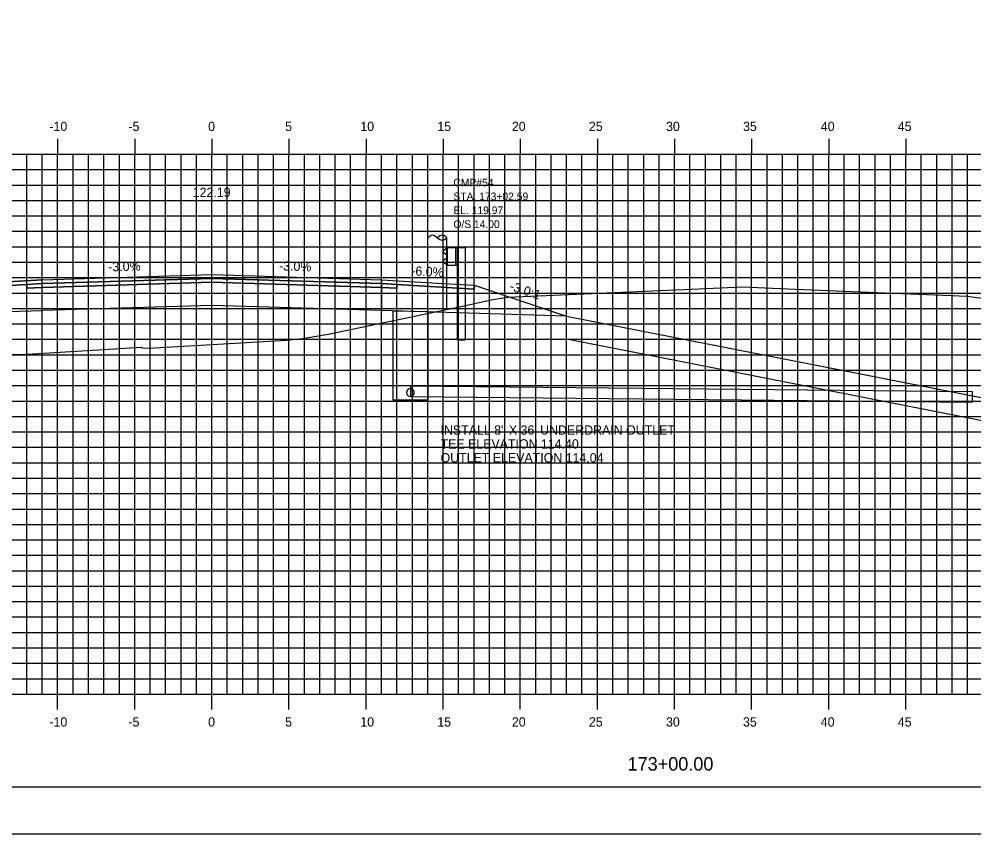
# Model space of a CAD drawing. Extents: x 850598 to 870284, y 366541 to 366651.
# Drawn here: x 856847.6 to 856909.5, y 366541.2 to 366594 of the extents above; entities that cross this region are included whole.
import ezdxf

# ---------------------------------------------------------------- set-up
doc = ezdxf.new("R2010")
doc.units = 0
for name, color, linetype in [('ANNOTATION', 7, 'Continuous'), ('BORDER', 7, 'Continuous'), ('D_Drainage_Culvert', 7, 'Continuous'), ('D_Drainage_RipRap', 7, 'Continuous'), ('D_Drainage_Underdrain', 7, 'Continuous'), ('D_Drainage_Underdrain_06in', 7, 'Continuous'), ('D_Guardrail_Beam_Rt', 7, 'Continuous'), ('D_Roadway_Centerline', 7, 'Continuous'), ('D_Roadway_Centerline_Text', 7, 'Continuous'), ('D_Roadway_Edge_Shoulder', 7, 'Continuous'), ('D_Roadway_Edge_TW', 7, 'Continuous'), ('D_Roadway_Pavement', 7, 'Continuous'), ('D_Roadway_SlopeLines', 7, 'Continuous'), ('D_Roadway_SubGrade', 7, 'Continuous'), ('D_Text_Monospaced', 7, 'Continuous'), ('H_V ANNOTATION', 7, 'Continuous'), ('MAJOR', 7, 'Continuous'), ('MINOR', 7, 'Continuous'), ('PLOT BOUNDARY', 7, 'Continuous'), ('S_Roadway_Centerline', 7, 'Continuous'), ('S_Utilities_Pole_Joint', 7, 'Continuous')]:
    doc.layers.add(name, color=color, linetype=linetype)

msp = doc.modelspace()

# ---------------------------------------------------------------- linework, layer by layer
at = {"layer": 'BORDER'}
msp.add_line((856815.08, 366544.225), (856975.08, 366544.225), dxfattribs=at)
at = {"layer": 'D_Drainage_Culvert'}
msp.add_lwpolyline([(856872.955, 366569.522), (856909.401, 366569.158), (856909.408, 366569.825), (856872.962, 366570.189)], close=True, dxfattribs=at)
at = {"layer": 'D_Drainage_RipRap'}
msp.add_lwpolyline([(856960.08, 366559.621), (856960.08, 366556.34), (856942.572, 366559.775), (856941.71, 366561.725), (856883.08, 366573.229), (856883.08, 366574.729), (856941.71, 366563.225)], close=True, dxfattribs=at)
at = {"layer": 'D_Drainage_Underdrain'}
msp.add_lwpolyline([(856874.08, 366575.022), (856874.08, 366569.272), (856871.83, 366569.272), (856871.83, 366575.067)], close=True, dxfattribs=at)
at = {"layer": 'D_Drainage_Underdrain_06in'}
msp.add_lwpolyline([(856872.955, 366570.022), (856872.878, 366570.01), (856872.808, 366569.975), (856872.753, 366569.919), (856872.717, 366569.85), (856872.705, 366569.772), (856872.717, 366569.695), (856872.753, 366569.625), (856872.808, 366569.57), (856872.878, 366569.535), (856872.955, 366569.522), (856873.032, 366569.535), (856873.102, 366569.57), (856873.157, 366569.625), (856873.193, 366569.695), (856873.205, 366569.772), (856873.193, 366569.85), (856873.157, 366569.919), (856873.102, 366569.975), (856873.032, 366570.01)], close=True, dxfattribs=at)
at = {"layer": 'D_Guardrail_Beam_Rt'}
for p, q in [((856875.261, 366579.088), (856875.118, 366578.988)), ((856875.118, 366578.845), (856875.313, 366578.709)), ((856875.351, 366579.108), (856875.278, 366579.095)), ((856875.347, 366578.645), (856875.347, 366578.553)), ((856875.351, 366579.182), (856876.039, 366579.182)), ((856875.351, 366578.016), (856875.351, 366579.182)), ((856875.872, 366579.182), (856875.872, 366578.016)), ((856875.976, 366579.182), (856875.976, 366578.016)), ((856876.039, 366579.182), (856876.509, 366579.182)), ((856876.039, 366579.182), (856876.039, 366578.016)), ((856876.509, 366579.182), (856876.509, 366573.182)), ((856875.313, 366578.489), (856875.118, 366578.353)), ((856875.118, 366578.21), (856875.261, 366578.11)), ((856875.278, 366578.103), (856875.351, 366578.09)), ((856876.039, 366578.016), (856875.351, 366578.016)), ((856876.018, 366573.182), (856876.018, 366578.016)), ((856876.018, 366573.182), (856876.509, 366573.182))]:
    msp.add_line(p, q, dxfattribs=at)
for centre, major_axis, start_param, end_param in [((856875.168, 366578.917), (-0.0877, 0), 5.323254, 7.243116), ((856875.285, 366579.054), (-0.0417, 0), 4.886922, 5.323254), ((856875.268, 366578.645), (0.0789, 0), 0, 0.959931), ((856875.168, 366578.281), (-0.0877, 0), 5.323254, 7.243116), ((856875.285, 366578.144), (-0.0417, 0), 0.959931, 1.396263), ((856875.268, 366578.553), (0.0789, 0), 5.323254, 6.283185)]:
    msp.add_ellipse(centre, major_axis=major_axis, ratio=0.995501, start_param=start_param, end_param=end_param, dxfattribs=at)
at = {"layer": 'D_Roadway_Centerline'}
msp.add_lwpolyline([(856829.42, 366572.013), (856829.835, 366571.992), (856830.25, 366571.917), (856830.665, 366571.79), (856831.08, 366571.609), (856837.336, 366574.737), (856841.08, 366576.609), (856843.08, 366576.729), (856849.08, 366577.089), (856860.08, 366577.419), (856871.08, 366577.089), (856875.08, 366576.849), (856877.08, 366576.729), (856883.08, 366574.729), (856941.71, 366563.225), (856960.08, 366559.621)], dxfattribs=at)
at = {"layer": 'D_Roadway_Edge_Shoulder'}
for points in [[(856849.08, 366577.089), (856843.08, 366576.729), (856843.08, 366576.729), (856841.08, 366576.609), (856841.08, 366576.359), (856848.08, 366576.779), (856849.08, 366576.839)], [(856871.08, 366577.089), (856875.08, 366576.849), (856875.08, 366576.849), (856877.08, 366576.729), (856877.08, 366576.479), (856872.08, 366576.779), (856871.08, 366576.839)]]:
    msp.add_lwpolyline(points, close=True, dxfattribs=at)
at = {"layer": 'D_Roadway_Edge_TW'}
msp.add_lwpolyline([(856849.08, 366576.839), (856849.08, 366577.089), (856860.08, 366577.419), (856871.08, 366577.089), (856871.08, 366576.839), (856860.08, 366577.169)], close=True, dxfattribs=at)
at = {"layer": 'D_Roadway_Pavement'}
for points in [[(856849.08, 366576.839), (856848.08, 366576.779), (856848.08, 366576.529), (856849.08, 366576.589)], [(856849.08, 366576.589), (856849.08, 366576.839), (856860.08, 366577.169), (856871.08, 366576.839), (856871.08, 366576.589), (856860.08, 366576.919)], [(856871.08, 366576.839), (856872.08, 366576.779), (856872.08, 366576.529), (856871.08, 366576.589)]]:
    msp.add_lwpolyline(points, close=True, dxfattribs=at)
at = {"layer": 'D_Roadway_SlopeLines'}
msp.add_lwpolyline([(856883.08, 366574.729), (856960.08, 366559.621)], dxfattribs=at)
at = {"layer": 'D_Roadway_SubGrade'}
for points in [[(856849.08, 366575.089), (856849.08, 366576.589), (856860.08, 366576.919), (856871.08, 366576.589), (856871.08, 366575.089), (856860.08, 366575.419)], [(856849.08, 366576.589), (856848.08, 366576.529), (856848.08, 366576.779), (856841.08, 366576.359), (856841.08, 366576.609), (856837.336, 366574.737), (856849.08, 366575.089)], [(856871.08, 366576.589), (856872.08, 366576.529), (856872.08, 366576.779), (856877.08, 366576.479), (856877.08, 366576.729), (856883.08, 366574.729), (856871.08, 366575.089)]]:
    msp.add_lwpolyline(points, close=True, dxfattribs=at)
at = {"layer": 'MAJOR'}
for p, q in [((856850.08, 366586.227), (856850.08, 366585.225)), ((856850.08, 366586.227), (856850.08, 366585.225)), ((856855.08, 366586.227), (856855.08, 366585.225)), ((856855.08, 366586.227), (856855.08, 366585.225)), ((856860.08, 366586.227), (856860.08, 366585.225)), ((856860.08, 366586.227), (856860.08, 366585.225)), ((856865.08, 366586.227), (856865.08, 366585.225)), ((856865.08, 366586.227), (856865.08, 366585.225)), ((856870.08, 366586.227), (856870.08, 366585.225)), ((856870.08, 366586.227), (856870.08, 366585.225)), ((856875.08, 366586.227), (856875.08, 366585.225)), ((856875.08, 366586.227), (856875.08, 366585.225)), ((856880.08, 366586.227), (856880.08, 366585.225)), ((856880.08, 366586.227), (856880.08, 366585.225)), ((856885.08, 366586.227), (856885.08, 366585.225)), ((856885.08, 366586.227), (856885.08, 366585.225)), ((856890.08, 366586.227), (856890.08, 366585.225)), ((856890.08, 366586.227), (856890.08, 366585.225)), ((856895.08, 366586.227), (856895.08, 366585.225)), ((856895.08, 366586.227), (856895.08, 366585.225)), ((856900.08, 366586.227), (856900.08, 366585.225)), ((856900.08, 366586.227), (856900.08, 366585.225)), ((856905.08, 366586.227), (856905.08, 366585.225)), ((856905.08, 366586.227), (856905.08, 366585.225)), ((856820.08, 366585.225), (856960.08, 366585.225)), ((856820.08, 366585.225), (856960.08, 366585.225)), ((856820.08, 366585.225), (856960.08, 366585.225)), ((856820.08, 366585.225), (856960.08, 366585.225)), ((856850.08, 366550.225), (856850.08, 366585.225)), ((856850.08, 366550.225), (856850.08, 366585.225)), ((856855.08, 366550.225), (856855.08, 366585.225)), ((856855.08, 366550.225), (856855.08, 366585.225)), ((856860.08, 366550.225), (856860.08, 366585.225)), ((856860.08, 366550.225), (856860.08, 366585.225)), ((856865.08, 366550.225), (856865.08, 366585.225)), ((856865.08, 366550.225), (856865.08, 366585.225)), ((856870.08, 366550.225), (856870.08, 366585.225)), ((856870.08, 366550.225), (856870.08, 366585.225)), ((856875.08, 366550.225), (856875.08, 366585.225)), ((856875.08, 366550.225), (856875.08, 366585.225)), ((856880.08, 366550.225), (856880.08, 366585.225)), ((856880.08, 366550.225), (856880.08, 366585.225)), ((856885.08, 366550.225), (856885.08, 366585.225)), ((856885.08, 366550.225), (856885.08, 366585.225)), ((856890.08, 366550.225), (856890.08, 366585.225)), ((856890.08, 366550.225), (856890.08, 366585.225)), ((856895.08, 366550.225), (856895.08, 366585.225)), ((856895.08, 366550.225), (856895.08, 366585.225)), ((856900.08, 366550.225), (856900.08, 366585.225)), ((856900.08, 366550.225), (856900.08, 366585.225)), ((856905.08, 366550.225), (856905.08, 366585.225)), ((856905.08, 366550.225), (856905.08, 366585.225)), ((856820.08, 366580.225), (856960.08, 366580.225)), ((856820.08, 366580.225), (856960.08, 366580.225)), ((856820.08, 366575.225), (856960.08, 366575.225)), ((856820.08, 366575.225), (856960.08, 366575.225)), ((856820.08, 366570.225), (856960.08, 366570.225)), ((856820.08, 366570.225), (856960.08, 366570.225)), ((856820.08, 366565.225), (856960.08, 366565.225)), ((856820.08, 366565.225), (856960.08, 366565.225)), ((856820.08, 366560.225), (856960.08, 366560.225)), ((856820.08, 366560.225), (856960.08, 366560.225)), ((856820.08, 366555.225), (856960.08, 366555.225)), ((856820.08, 366555.225), (856960.08, 366555.225)), ((856820.08, 366550.225), (856960.08, 366550.225)), ((856820.08, 366550.225), (856960.08, 366550.225)), ((856820.08, 366550.225), (856960.08, 366550.225)), ((856820.08, 366550.225), (856960.08, 366550.225)), ((856850.08, 366549.223), (856850.08, 366550.225)), ((856850.08, 366549.223), (856850.08, 366550.225)), ((856855.08, 366549.223), (856855.08, 366550.225)), ((856855.08, 366549.223), (856855.08, 366550.225)), ((856860.08, 366549.223), (856860.08, 366550.225)), ((856860.08, 366549.223), (856860.08, 366550.225)), ((856865.08, 366549.223), (856865.08, 366550.225)), ((856865.08, 366549.223), (856865.08, 366550.225)), ((856870.08, 366549.223), (856870.08, 366550.225)), ((856870.08, 366549.223), (856870.08, 366550.225)), ((856875.08, 366549.223), (856875.08, 366550.225)), ((856875.08, 366549.223), (856875.08, 366550.225)), ((856880.08, 366549.223), (856880.08, 366550.225)), ((856880.08, 366549.223), (856880.08, 366550.225)), ((856885.08, 366549.223), (856885.08, 366550.225)), ((856885.08, 366549.223), (856885.08, 366550.225)), ((856890.08, 366549.223), (856890.08, 366550.225)), ((856890.08, 366549.223), (856890.08, 366550.225)), ((856895.08, 366549.223), (856895.08, 366550.225)), ((856895.08, 366549.223), (856895.08, 366550.225)), ((856900.08, 366549.223), (856900.08, 366550.225)), ((856900.08, 366549.223), (856900.08, 366550.225)), ((856905.08, 366549.223), (856905.08, 366550.225)), ((856905.08, 366549.223), (856905.08, 366550.225))]:
    msp.add_line(p, q, dxfattribs=at)
at = {"layer": 'MINOR'}
for p, q in [((856848.08, 366550.225), (856848.08, 366585.225)), ((856848.08, 366550.225), (856848.08, 366585.225)), ((856849.08, 366550.225), (856849.08, 366585.225)), ((856849.08, 366550.225), (856849.08, 366585.225)), ((856851.08, 366550.225), (856851.08, 366585.225)), ((856851.08, 366550.225), (856851.08, 366585.225)), ((856852.08, 366550.225), (856852.08, 366585.225)), ((856852.08, 366550.225), (856852.08, 366585.225)), ((856853.08, 366550.225), (856853.08, 366585.225)), ((856853.08, 366550.225), (856853.08, 366585.225)), ((856854.08, 366550.225), (856854.08, 366585.225)), ((856854.08, 366550.225), (856854.08, 366585.225)), ((856856.08, 366550.225), (856856.08, 366585.225)), ((856856.08, 366550.225), (856856.08, 366585.225)), ((856857.08, 366550.225), (856857.08, 366585.225)), ((856857.08, 366550.225), (856857.08, 366585.225)), ((856858.08, 366550.225), (856858.08, 366585.225)), ((856858.08, 366550.225), (856858.08, 366585.225)), ((856859.08, 366550.225), (856859.08, 366585.225)), ((856859.08, 366550.225), (856859.08, 366585.225)), ((856861.08, 366550.225), (856861.08, 366585.225)), ((856861.08, 366550.225), (856861.08, 366585.225)), ((856862.08, 366550.225), (856862.08, 366585.225)), ((856862.08, 366550.225), (856862.08, 366585.225)), ((856863.08, 366550.225), (856863.08, 366585.225)), ((856863.08, 366550.225), (856863.08, 366585.225)), ((856864.08, 366550.225), (856864.08, 366585.225)), ((856864.08, 366550.225), (856864.08, 366585.225)), ((856866.08, 366550.225), (856866.08, 366585.225)), ((856866.08, 366550.225), (856866.08, 366585.225)), ((856867.08, 366550.225), (856867.08, 366585.225)), ((856867.08, 366550.225), (856867.08, 366585.225)), ((856868.08, 366550.225), (856868.08, 366585.225)), ((856868.08, 366550.225), (856868.08, 366585.225)), ((856869.08, 366550.225), (856869.08, 366585.225)), ((856869.08, 366550.225), (856869.08, 366585.225)), ((856871.08, 366550.225), (856871.08, 366585.225)), ((856871.08, 366550.225), (856871.08, 366585.225)), ((856872.08, 366550.225), (856872.08, 366585.225)), ((856872.08, 366550.225), (856872.08, 366585.225)), ((856873.08, 366550.225), (856873.08, 366585.225)), ((856873.08, 366550.225), (856873.08, 366585.225)), ((856874.08, 366550.225), (856874.08, 366585.225)), ((856874.08, 366550.225), (856874.08, 366585.225)), ((856876.08, 366550.225), (856876.08, 366585.225)), ((856876.08, 366550.225), (856876.08, 366585.225)), ((856877.08, 366550.225), (856877.08, 366585.225)), ((856877.08, 366550.225), (856877.08, 366585.225)), ((856878.08, 366550.225), (856878.08, 366585.225)), ((856878.08, 366550.225), (856878.08, 366585.225)), ((856879.08, 366550.225), (856879.08, 366585.225)), ((856879.08, 366550.225), (856879.08, 366585.225)), ((856881.08, 366550.225), (856881.08, 366585.225)), ((856881.08, 366550.225), (856881.08, 366585.225)), ((856882.08, 366550.225), (856882.08, 366585.225)), ((856882.08, 366550.225), (856882.08, 366585.225)), ((856883.08, 366550.225), (856883.08, 366585.225)), ((856883.08, 366550.225), (856883.08, 366585.225)), ((856884.08, 366550.225), (856884.08, 366585.225)), ((856884.08, 366550.225), (856884.08, 366585.225)), ((856886.08, 366550.225), (856886.08, 366585.225)), ((856886.08, 366550.225), (856886.08, 366585.225)), ((856887.08, 366550.225), (856887.08, 366585.225)), ((856887.08, 366550.225), (856887.08, 366585.225)), ((856888.08, 366550.225), (856888.08, 366585.225)), ((856888.08, 366550.225), (856888.08, 366585.225)), ((856889.08, 366550.225), (856889.08, 366585.225)), ((856889.08, 366550.225), (856889.08, 366585.225)), ((856891.08, 366550.225), (856891.08, 366585.225)), ((856891.08, 366550.225), (856891.08, 366585.225)), ((856892.08, 366550.225), (856892.08, 366585.225)), ((856892.08, 366550.225), (856892.08, 366585.225)), ((856893.08, 366550.225), (856893.08, 366585.225)), ((856893.08, 366550.225), (856893.08, 366585.225)), ((856894.08, 366550.225), (856894.08, 366585.225)), ((856894.08, 366550.225), (856894.08, 366585.225)), ((856896.08, 366550.225), (856896.08, 366585.225)), ((856896.08, 366550.225), (856896.08, 366585.225)), ((856897.08, 366550.225), (856897.08, 366585.225)), ((856897.08, 366550.225), (856897.08, 366585.225)), ((856898.08, 366550.225), (856898.08, 366585.225)), ((856898.08, 366550.225), (856898.08, 366585.225)), ((856899.08, 366550.225), (856899.08, 366585.225)), ((856899.08, 366550.225), (856899.08, 366585.225)), ((856901.08, 366550.225), (856901.08, 366585.225)), ((856901.08, 366550.225), (856901.08, 366585.225)), ((856902.08, 366550.225), (856902.08, 366585.225)), ((856902.08, 366550.225), (856902.08, 366585.225)), ((856903.08, 366550.225), (856903.08, 366585.225)), ((856903.08, 366550.225), (856903.08, 366585.225)), ((856904.08, 366550.225), (856904.08, 366585.225)), ((856904.08, 366550.225), (856904.08, 366585.225)), ((856906.08, 366550.225), (856906.08, 366585.225)), ((856906.08, 366550.225), (856906.08, 366585.225)), ((856907.08, 366550.225), (856907.08, 366585.225)), ((856907.08, 366550.225), (856907.08, 366585.225)), ((856908.08, 366550.225), (856908.08, 366585.225)), ((856908.08, 366550.225), (856908.08, 366585.225)), ((856909.08, 366550.225), (856909.08, 366585.225)), ((856909.08, 366550.225), (856909.08, 366585.225)), ((856820.08, 366584.225), (856960.08, 366584.225)), ((856820.08, 366584.225), (856960.08, 366584.225)), ((856820.08, 366583.225), (856960.08, 366583.225)), ((856820.08, 366583.225), (856960.08, 366583.225)), ((856820.08, 366582.225), (856960.08, 366582.225)), ((856820.08, 366582.225), (856960.08, 366582.225)), ((856820.08, 366581.225), (856960.08, 366581.225)), ((856820.08, 366581.225), (856960.08, 366581.225)), ((856820.08, 366579.225), (856960.08, 366579.225)), ((856820.08, 366579.225), (856960.08, 366579.225)), ((856820.08, 366578.225), (856960.08, 366578.225)), ((856820.08, 366578.225), (856960.08, 366578.225)), ((856820.08, 366577.225), (856960.08, 366577.225)), ((856820.08, 366577.225), (856960.08, 366577.225)), ((856820.08, 366576.225), (856960.08, 366576.225)), ((856820.08, 366576.225), (856960.08, 366576.225)), ((856820.08, 366574.225), (856960.08, 366574.225)), ((856820.08, 366574.225), (856960.08, 366574.225)), ((856820.08, 366573.225), (856960.08, 366573.225)), ((856820.08, 366573.225), (856960.08, 366573.225)), ((856820.08, 366572.225), (856960.08, 366572.225)), ((856820.08, 366572.225), (856960.08, 366572.225)), ((856820.08, 366571.225), (856960.08, 366571.225)), ((856820.08, 366571.225), (856960.08, 366571.225)), ((856820.08, 366569.225), (856960.08, 366569.225)), ((856820.08, 366569.225), (856960.08, 366569.225)), ((856820.08, 366568.225), (856960.08, 366568.225)), ((856820.08, 366568.225), (856960.08, 366568.225)), ((856820.08, 366567.225), (856960.08, 366567.225)), ((856820.08, 366567.225), (856960.08, 366567.225)), ((856820.08, 366566.225), (856960.08, 366566.225)), ((856820.08, 366566.225), (856960.08, 366566.225)), ((856820.08, 366564.225), (856960.08, 366564.225)), ((856820.08, 366564.225), (856960.08, 366564.225)), ((856820.08, 366563.225), (856960.08, 366563.225)), ((856820.08, 366563.225), (856960.08, 366563.225)), ((856820.08, 366562.225), (856960.08, 366562.225)), ((856820.08, 366562.225), (856960.08, 366562.225)), ((856820.08, 366561.225), (856960.08, 366561.225)), ((856820.08, 366561.225), (856960.08, 366561.225)), ((856820.08, 366559.225), (856960.08, 366559.225)), ((856820.08, 366559.225), (856960.08, 366559.225)), ((856820.08, 366558.225), (856960.08, 366558.225)), ((856820.08, 366558.225), (856960.08, 366558.225)), ((856820.08, 366557.225), (856960.08, 366557.225)), ((856820.08, 366557.225), (856960.08, 366557.225)), ((856820.08, 366556.225), (856960.08, 366556.225)), ((856820.08, 366556.225), (856960.08, 366556.225)), ((856820.08, 366554.225), (856960.08, 366554.225)), ((856820.08, 366554.225), (856960.08, 366554.225)), ((856820.08, 366553.225), (856960.08, 366553.225)), ((856820.08, 366553.225), (856960.08, 366553.225)), ((856820.08, 366552.225), (856960.08, 366552.225)), ((856820.08, 366552.225), (856960.08, 366552.225)), ((856820.08, 366551.225), (856960.08, 366551.225)), ((856820.08, 366551.225), (856960.08, 366551.225))]:
    msp.add_line(p, q, dxfattribs=at)
at = {"layer": 'PLOT BOUNDARY'}
msp.add_lwpolyline([(856806.987, 366541.166), (856976.987, 366541.166), (856976.987, 366651.166), (856806.987, 366651.166)], close=True, dxfattribs=at)
at = {"layer": 'S_Roadway_Centerline'}
msp.add_lwpolyline([(856820.08, 366572.044), (856820.304, 366572.047), (856823.3, 366571.929), (856848.13, 366572.268), (856855.509, 366572.72), (856855.578, 366572.662), (856856.009, 366572.658), (856864.925, 366573.173), (856865.77, 366573.248), (856865.843, 366573.256), (856867.628, 366573.564), (856876.329, 366575.364), (856878.302, 366575.805), (856879.27, 366575.945), (856891.152, 366576.471), (856894.488, 366576.633), (856897.909, 366576.483), (856909.072, 366576.016), (856912.792, 366575.511)], dxfattribs=at)
at = {"layer": 'S_Utilities_Pole_Joint'}
for p, q in [((856874.076, 366579.811), (856874.233, 366579.921)), ((856874.545, 366579.921), (856874.701, 366579.811)), ((856874.858, 366579.921), (856874.701, 366579.811)), ((856875.326, 366579.811), (856875.17, 366579.921)), ((856874.076, 366575.191), (856874.073, 366579.811)), ((856874.701, 366579.811), (856874.858, 366579.7)), ((856875.17, 366579.7), (856875.326, 366579.811)), ((856875.326, 366575.191), (856875.323, 366579.811))]:
    msp.add_line(p, q, dxfattribs=at)
for centre, start, end in [((856874.389, 366579.7), 90, 125.26439), ((856874.389, 366579.7), 54.73561, 90), ((856875.014, 366579.7), 90, 125.26439), ((856875.014, 366579.7), 54.73561, 90), ((856875.014, 366579.921), 234.73561, 270), ((856875.014, 366579.921), 270, 305.26439)]:
    msp.add_arc(centre, 0.271, start, end, dxfattribs=at)

# ---------------------------------------------------------------- texts
at = {"layer": 'ANNOTATION'}
for s, rotation, p in [('-3.0%', 1.71836, (856853.368, 366577.618)), ('-3.0%', 358.28164, (856864.428, 366577.689)), ('-6.0%', 356.56637, (856872.997, 366577.376)), ('-3.0:1', 341.56507, (856879.334, 366576.432))]:
    msp.add_text(s, height=0.6, rotation=rotation, dxfattribs=at).set_placement(p)
at = {"layer": 'D_Roadway_Centerline'}
for s, p in [('C', (856860.075, 366577.419)), ('C', (856860.075, 366577.419)), ('L', (856860.08, 366577.412)), ('L', (856860.08, 366577.412))]:
    msp.add_text(s, height=0.0146, dxfattribs=at).set_placement(p)
at = {"layer": 'D_Roadway_Centerline_Text'}
msp.add_text('122.19', height=0.6, dxfattribs=at).set_placement((856858.839, 366582.451))
at = {"layer": 'D_Text_Monospaced'}
for s, height, p in [('CMP#54 ', 0.5, (856875.743, 366583.136)), ('STA. 173+02.59', 0.49998, (856875.743, 366582.236)), ('EL. 119.97', 0.498, (856875.744, 366581.338)), ('O/S 14.00', 0.498, (856875.744, 366580.438))]:
    msp.add_text(s, height=height, dxfattribs=at).set_placement(p)
at = {"layer": 'H_V ANNOTATION'}
for s, height, p in [('-10', 0.6, (856849.545, 366586.725)), ('-5', 0.6, (856854.671, 366586.725)), ('0', 0.6, (856859.839, 366586.725)), ('5', 0.6, (856864.831, 366586.725)), ('10', 0.6, (856869.706, 366586.725)), ('15', 0.6, (856874.698, 366586.725)), ('20', 0.6, (856879.534, 366586.725)), ('25', 0.6, (856884.526, 366586.725)), ('30', 0.6, (856889.529, 366586.725)), ('35', 0.6, (856894.521, 366586.725)), ('40', 0.6, (856899.566, 366586.725)), ('45', 0.6, (856904.558, 366586.725)), ('INSTALL 8" X 36\' UNDERDRAIN OUTLET', 0.6, (856874.909, 366567.046)), ('TEE ELEVATION 114.40', 0.6, (856874.909, 366566.146)), ('OUTLET ELEVATION 114.04', 0.6, (856874.909, 366565.246)), ('-10', 0.6, (856849.545, 366548.125)), ('-5', 0.6, (856854.671, 366548.125)), ('0', 0.6, (856859.839, 366548.125)), ('5', 0.6, (856864.831, 366548.125)), ('10', 0.6, (856869.706, 366548.125)), ('15', 0.6, (856874.698, 366548.125)), ('20', 0.6, (856879.534, 366548.125)), ('25', 0.6, (856884.526, 366548.125)), ('30', 0.6, (856889.529, 366548.125)), ('35', 0.6, (856894.521, 366548.125)), ('40', 0.6, (856899.566, 366548.125)), ('45', 0.6, (856904.558, 366548.125)), ('173+00.00', 0.875, (856887.037, 366545.268))]:
    msp.add_text(s, height=height, dxfattribs=at).set_placement(p)
at = {"layer": 'S_Roadway_Centerline'}
for s, p in [('C', (856894.483, 366576.633)), ('L', (856894.488, 366576.626))]:
    msp.add_text(s, height=0.0146, dxfattribs=at).set_placement(p)

doc.saveas('drawing.dxf')
